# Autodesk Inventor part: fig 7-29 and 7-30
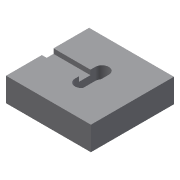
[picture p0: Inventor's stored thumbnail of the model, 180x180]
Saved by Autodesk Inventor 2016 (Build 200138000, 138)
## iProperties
Created: 2004-05
Part Number: fig 7-29 and 7-30
Document SubType Name: Modeling
Designer: CADCIM Technologies
Manufacturer: Standard
Standards Organization: Custom
Density: 1 g/cm^3
Material: Generic
Appearance: Default
Author: CADCIM Technologies
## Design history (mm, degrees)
sketch "Sketch1"
  geometry: L1 (-30.233, -25.517)-(22.302, -25.517); L2 (22.302, -25.517)-(22.302, 25.904); L3 (22.302, 25.904)-(-30.233, 25.904); L4 (-30.233, 25.904)-(-30.233, -25.517)
  constraints: 8 end point, 2 parallel, 1 horizontal, 1 perpendicular
extrude "Extrusion1" new body sketch "Sketch1" distance "d0" = 14.75; taper "d1" = 0 deg
sketch "Sketch2"
  geometry: L1 (1.047, -5.75)-(1.047, 6.846); L2 (-7.35, 6.845)-(-7.35, -5.75); A1 r 4.198 centre (-3.152, 6.846) between (1.047, 6.846) and (-7.35, 6.845); A2 r 4.198 centre (-3.152, -5.75) between (-7.35, -5.75) and (1.047, -5.75)
  constraints: 4 end point, 4 point on circle, 4 tangent, 2 centre point, 1 parallel
extrude "Extrusion2" cut sketch "Sketch2" distance "d2" = 7.5; taper "d3" = 0 deg
sketch "Sketch3"
  geometry: L1 (-7.5, 0)-(-7.5, 12.595) reference; L2 (-7.5, 0)-(0, 0) reference; L3 (-7.5, 2.416)-(-4.537, 2.416); L4 (-4.537, 2.416)-(-4.537, 9.616); L5 (-4.537, 9.616)-(-7.5, 9.616)
  constraints: 6 end point, 2 perpendicular, 2 point on line, 1 parallel
extrude "Extrusion3" cut sketch "Sketch3" stored distance "d4" = 6.75; taper "d5" = 0 deg
body "Solid1"
